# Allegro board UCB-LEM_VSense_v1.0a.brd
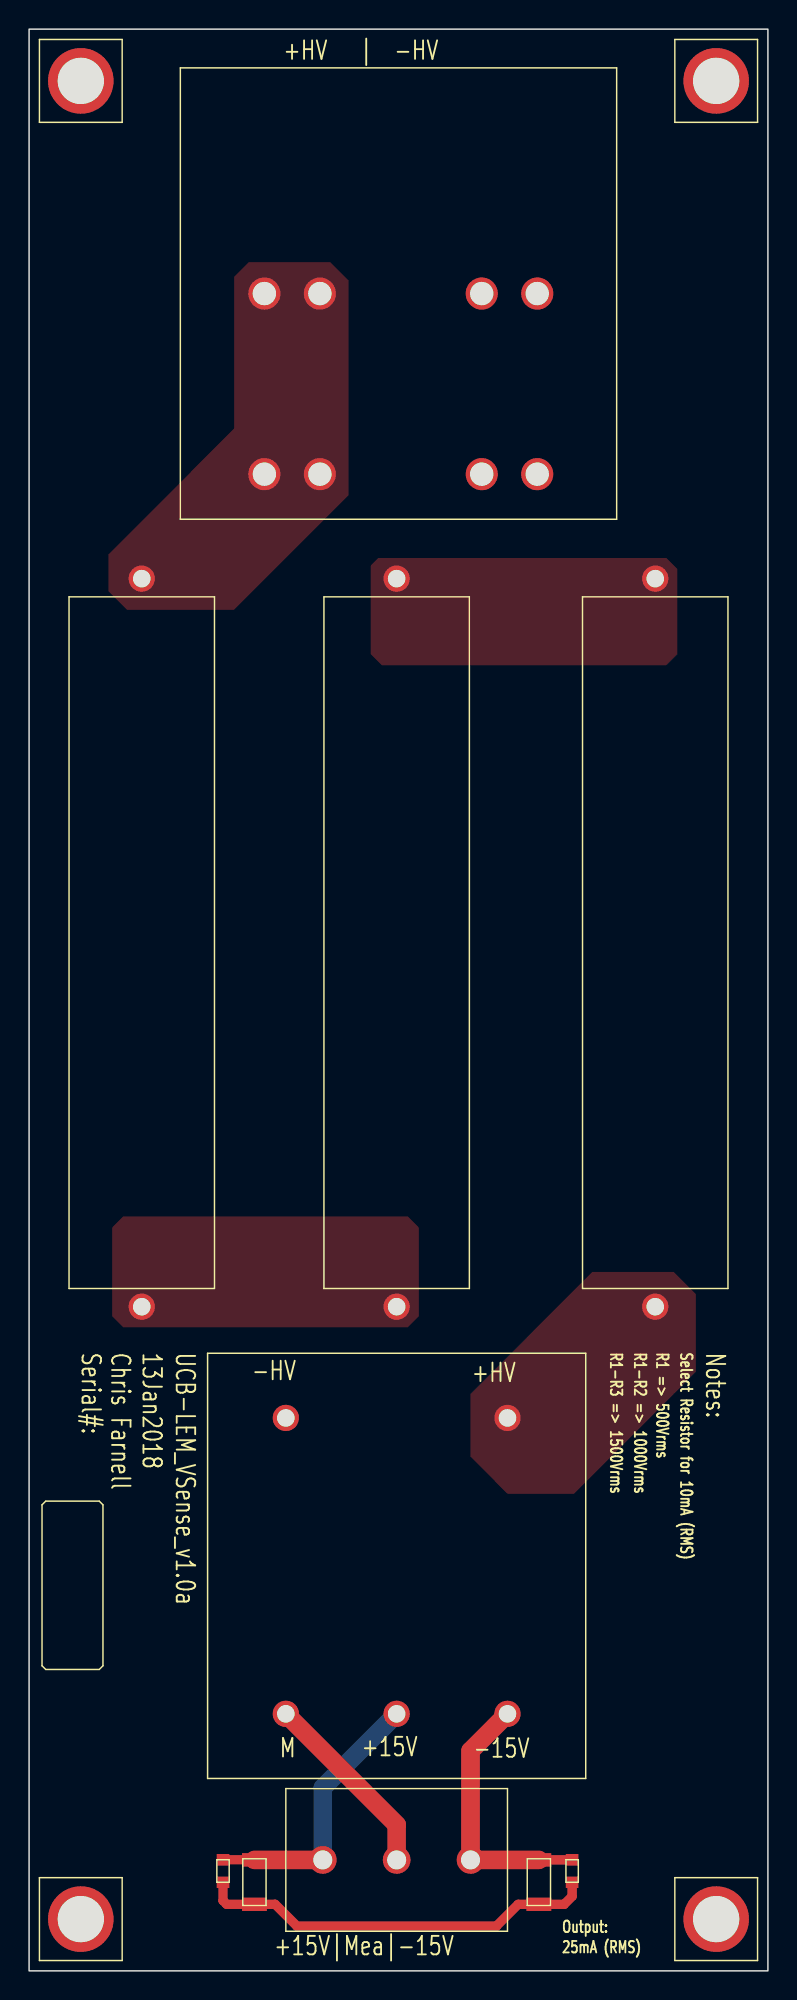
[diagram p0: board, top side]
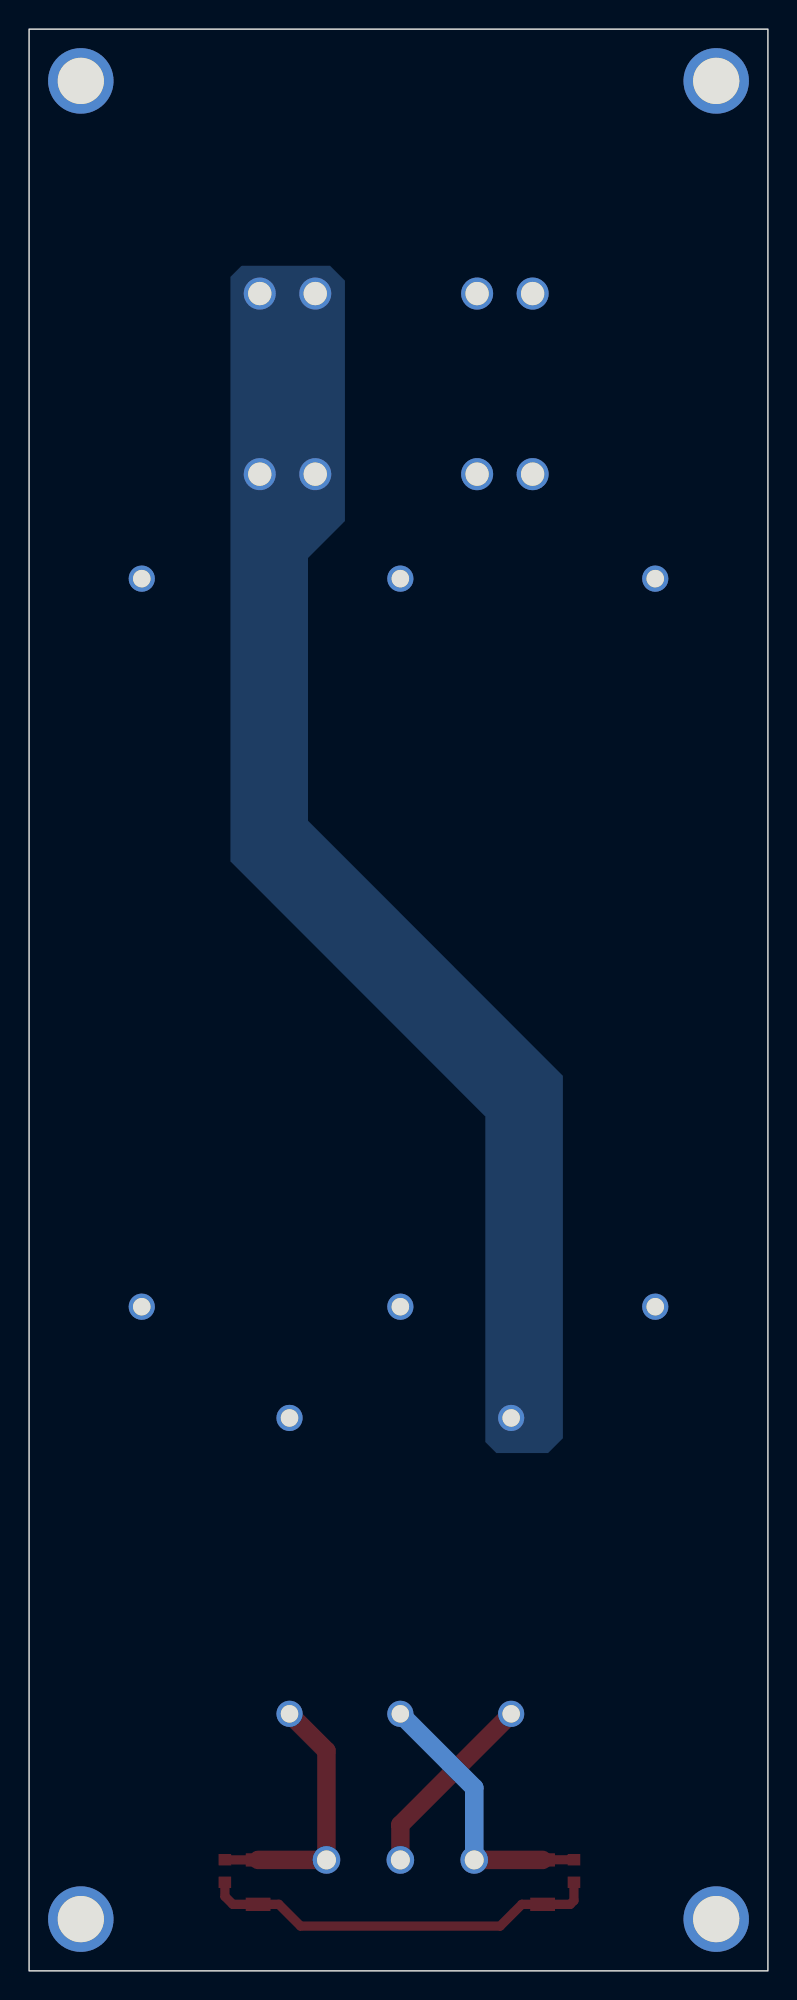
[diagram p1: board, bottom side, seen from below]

Outline 50.8 x 133.35 mm; copper layers: TOP, BOTTOM. Coordinates in mm from the lower left corner of the outline.
Outline path: rectangle 0,0 50.8,133.35

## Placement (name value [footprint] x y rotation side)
C1  10uF  [C_1206]  15.49 6.1 270 top
C2  10uF  [C_1206]  35.05 6.1 90 top
C3  0.1uF  [C_0603]  13.34 6.86 270 top
C4  0.1uF  [C_0603]  37.34 6.86 90 top
J1  -  [1715734]  25.27 7.62 90 top
J2  1932588  [PHOENIX_1932588]  25.4 115.19 0 top
MECH1  Mech_Hole  [4-40_SCREW]  3.56 129.79 0 top
MECH2  Mech_Hole  [4-40_SCREW]  47.24 129.79 0 top
MECH3  Mech_Hole  [4-40_SCREW]  47.24 3.56 0 top
MECH4  Mech_Hole  [4-40_SCREW]  3.56 3.56 0 top
R1  50k  [R_RS10]  7.75 70.61 90 top
R2  50k  [R_RS10]  25.27 70.61 270 top
R3  50k  [R_RS10]  43.05 70.61 90 top
U1  LEM LV 25-P  [LEM_LV-25-P]  25.27 27.81 0 top

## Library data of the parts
C1-C4 = CAP NP
J1 = Connector-3
J2 = HV_Connector-2
MECH1-MECH4 = Mech_Hole
R1-R3 = R-Standard
U1 = LEM-LV25-P

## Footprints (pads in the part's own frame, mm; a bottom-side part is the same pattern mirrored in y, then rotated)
4-40_SCREW
  round 4.5 hole 3.175: 1(0,0)
1715734
  round 1.9 hole 1.3: 1(0,5.08) 2(0,0) 3(0,-5.08)
C_0603
  rect 0.787x0.864 smd: 1(-0.775,0) 2(0.775,0)
C_1206
  rect 0.914x1.702 smd: 1(-1.524,0) 2(1.524,0)
LEM_LV-25-P
  round 1.8 hole 1.2: 1(-7.62,10.16) 2(7.62,10.16) 3(-7.62,-10.16) 4(0,-10.16) 5(7.62,-10.16)
PHOENIX_1932588
  round 2.2 hole 1.6: 1(-9.222,0) 2(-5.406,0) 3(-9.222,-12.402) 4(-5.406,-12.402) 5(5.724,0) 6(9.54,0) 7(5.724,-12.402) 8(9.54,-12.402)
R_RS10
  round 1.8 hole 1.2: 1(-25,0) 2(25,0)

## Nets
+15V: C1.1 C3.1 J1.1(P1) U1.4(+15V)
-15V: C2.2 C4.2 J1.3(P3) U1.5(-15V)
MEA: J1.2(P2) U1.3(M)
N61188: C1.2 C2.1 C3.2 C4.1
N61680: J2.1(P1_1) J2.2(P1_2) J2.3(P1_3) J2.4(P1_4) R1.2
N61699: R1.1 R2.2
N61724: R2.1 R3.2
N61749: R3.1 U1.2(+HV)
N61761: J2.5(P2_1) J2.6(P2_2) J2.7(P2_3) J2.8(P2_4) U1.1(-HV)

Pads without a net: MECH1 1; MECH2 1; MECH3 1; MECH4 1

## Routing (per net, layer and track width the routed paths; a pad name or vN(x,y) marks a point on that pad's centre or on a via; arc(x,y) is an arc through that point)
+15V: length 19
  TOP w0.635: C3.1 15.48,7.63 C1.1
  TOP w1.27: J1.1 C1.1
  BOTTOM w1.27: J1.1 20.19,12.57 U1.4
-15V: length 18.1
  TOP w0.635: C2.2 37.34,7.62 C4.2
  TOP w1.27: C2.2 J1.3 30.35,15.11 U1.5
MEA: length 13.2
  TOP w1.27: J1.2 25.27,10.03 U1.3
N61188: length 27.8
  TOP w0.635: C3.2 13.34,4.83 13.59,4.57 C1.2 16.92,4.57 18.42,3.07 32.13,3.07 33.63,4.57 C2.1 36.79,4.57 37.34,5.12 C4.1

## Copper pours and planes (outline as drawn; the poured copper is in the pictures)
N61680 on TOP: 21.97,101.35 21.97,116.08 20.7,117.35 15.11,117.35 14.1,116.33 14.1,105.92 5.46,97.28 5.46,94.74 6.73,93.47 14.1,93.47
N61699 on TOP: 26.04,44.2 26.8,44.96 26.8,51.05 26.04,51.82 6.48,51.82 5.72,51.05 5.72,44.96 6.48,44.2
N61724 on TOP: 43.81,89.66 44.58,90.42 44.58,96.27 43.81,97.03 24,97.03 23.5,96.52 23.5,90.42 24.26,89.66
N61749 on TOP: 37.47,32.77 45.85,41.15 45.85,46.48 44.32,48.01 38.74,48.01 30.35,39.62 30.35,35.31 32.89,32.77
N61761 on BOTTOM: 36.96,116.33 36.19,117.09 30.1,117.09 29.08,116.08 29.08,99.57 31.62,97.03 31.62,78.99 14.1,61.47 14.1,36.58 15.11,35.56 18.67,35.56 19.43,36.32 19.43,58.67 36.96,76.2

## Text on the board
Ref Des/Silkscreen Top: Output: | 25mA (RMS) | R1-R3 => 1500Vrms | R1-R2 => 1000Vrms | R1 => 500Vrms | Select Resistor for 10mA (RMS) | +15V|Mea|-15V | +HV   |  -HV | Serial#: | Chris Farnell | 13Jan2018 | UCB-LEM_VSense_v1.0a | Notes:
